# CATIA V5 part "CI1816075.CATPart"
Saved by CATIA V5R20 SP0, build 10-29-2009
Part number: CI1816075
Bounding box of the stored display mesh (mm): x -15 to 15, y -11.308 to 99, z -19.756 to 16.81
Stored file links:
  C:\Users\Raffaele\Desktop\3D X SITO CF\BOLEX\19-INCLINED ASSEMBLY REF_CI\CI1816075.CATPart

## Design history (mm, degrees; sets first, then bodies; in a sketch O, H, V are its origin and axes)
Set1
  DatumSurface1 to DatumSurface16 "MANIFOLD_SOLID_BREP #381"
  DatumSurface17 to DatumSurface39 "MANIFOLD_SOLID_BREP #1106"
Body1 (main body)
